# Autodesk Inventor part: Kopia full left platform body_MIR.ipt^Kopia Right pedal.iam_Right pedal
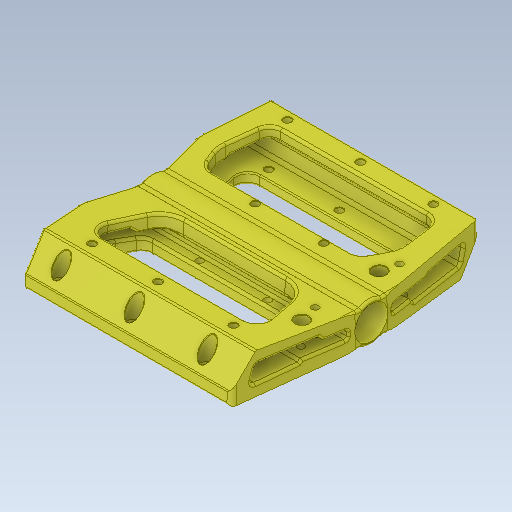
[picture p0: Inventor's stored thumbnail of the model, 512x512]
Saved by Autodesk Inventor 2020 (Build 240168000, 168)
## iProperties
Created: 2017-10
Part Number: Kopia full left platform body_MIR.ipt^Kopia Right pedal.iam_Right pedal
Material: solidworks materials|7075-T6 (SN)|177
Document SubType Name: Modeling
Designer: Tomasz
Density: 2.81 g/cm^3
Appearance: 0,0,0
Sending System: SolidWorks 2017
Last Author: Tomasz
Last Saved: 2017-11-19
Author: Tomasz
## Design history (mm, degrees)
feature "full left platform body_MIR.ipt"
node "Bryła1"
